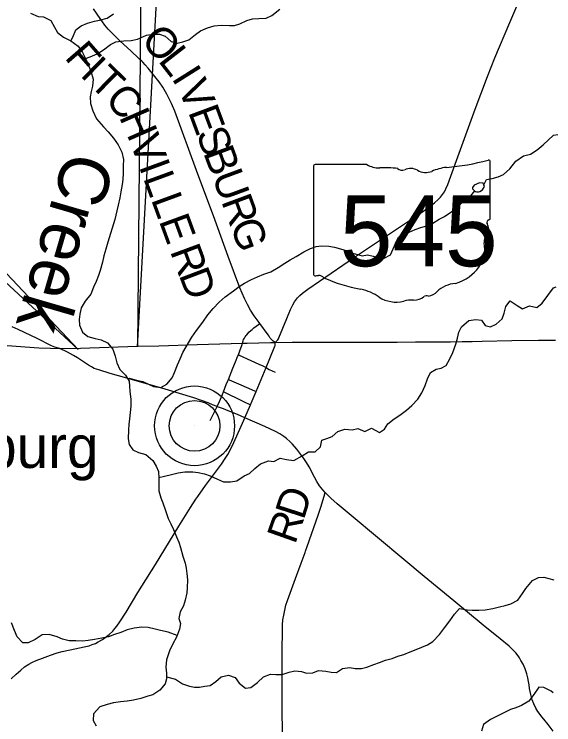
# Model space of a CAD drawing. Extents: x 0 to 34, y 0 to 22.
# Drawn here: x 6.497 to 7.503, y 16.591 to 17.915 of the extents above; entities that cross this region are included whole.
import ezdxf

# ---------------------------------------------------------------- set-up
doc = ezdxf.new("R2010")
doc.units = 0
for name, color, linetype in [('Default', 7, 'Continuous'), ('GM_X_County_Road', 7, 'Continuous'), ('GM_X_County_Road_Text', 7, 'Continuous'), ('GM_X_Minor_Lake', 7, 'Continuous'), ('GM_X_Minor_River', 7, 'Continuous'), ('GM_X_Minor_River_Text', 7, 'Continuous'), ('GM_X_State_Location', 7, 'Continuous'), ('GM_X_State_Route', 7, 'Continuous'), ('GM_X_State_Shield', 7, 'Continuous'), ('GM_X_Township_Road', 7, 'Continuous'), ('GM_X_Township_Road_Text', 7, 'Continuous'), ('GM_X_Unincorporated', 7, 'Continuous'), ('GM_X_Unincorporated_Location', 7, 'Continuous'), ('GM_X_Unincorporated_Text', 7, 'Continuous')]:
    doc.layers.add(name, color=color, linetype=linetype)

msp = doc.modelspace()

# ---------------------------------------------------------------- linework, layer by layer
at = {"layer": 'Default'}
for points in [[(6.7366, 18.3097), (6.7269, 17.2952), (6.7828, 18.3097)], [(6.2148, 17.662), (6.6166, 17.2903), (6.2148, 17.7158)]]:
    msp.add_lwpolyline(points, close=True, dxfattribs=at)
at = {"layer": 'GM_X_County_Road'}
for points in [[(6.9547, 17.3388), (6.9536, 17.3403), (6.9446, 17.3529), (6.9379, 17.3633), (6.9319, 17.3741), (6.9264, 17.3852), (6.9176, 17.4052), (6.8962, 17.4634), (6.8686, 17.5393), (6.8545, 17.5772), (6.8372, 17.6238), (6.7964, 17.7345), (6.7904, 17.7488), (6.7864, 17.7573), (6.782, 17.7656), (6.774, 17.7788), (6.7672, 17.7888), (6.7597, 17.7987), (6.752, 17.8082), (6.7496, 17.8109), (6.7471, 17.8143), (6.7415, 17.8206), (6.7371, 17.8253), (6.7352, 17.8273), (6.7311, 17.8312), (6.7297, 17.8326), (6.7147, 17.8463), (6.6947, 17.8646), (6.6822, 17.8767), (6.6722, 17.8872), (6.6664, 17.8944), (6.6573, 17.9069), (6.6453, 17.9247)], [(6.9838, 17.3036), (6.9801, 17.3059), (6.9779, 17.3076), (6.9745, 17.3117), (6.9721, 17.3153), (6.9703, 17.3178), (6.9547, 17.3388)]]:
    msp.add_lwpolyline(points, dxfattribs=at)
at = {"layer": 'GM_X_Minor_Lake'}
for points in [[(7.3649, 17.5845), (7.3695, 17.5875), (7.3733, 17.594), (7.3707, 17.6004), (7.3639, 17.6009), (7.354, 17.5964), (7.3513, 17.5918)], [(7.3513, 17.5918), (7.3514, 17.5898), (7.3526, 17.5882), (7.3549, 17.5859), (7.357, 17.5843), (7.3595, 17.5837), (7.3624, 17.5837), (7.3649, 17.5845)], [(7.5016, 16.6509), (7.4975, 16.6538), (7.4842, 16.6607), (7.4747, 16.6612), (7.4655, 16.6475), (7.456, 16.6351), (7.4423, 16.6272), (7.432, 16.623), (7.4218, 16.6197), (7.4092, 16.6137), (7.3971, 16.6073), (7.3849, 16.6013), (7.3716, 16.5918), (7.3677, 16.5793)]]:
    msp.add_lwpolyline(points, dxfattribs=at)
at = {"layer": 'GM_X_Minor_River'}
for points in [[(6.6301, 17.8324), (6.6387, 17.8356), (6.652, 17.8408), (6.6638, 17.8487), (6.6768, 17.8582), (6.6867, 17.8631), (6.7019, 17.8653), (6.7155, 17.8659), (6.7273, 17.8682), (6.744, 17.8757), (6.7554, 17.8775), (6.7683, 17.8778), (6.7785, 17.8736), (6.7899, 17.8637), (6.8013, 17.8606), (6.8115, 17.8632), (6.8225, 17.8669), (6.8351, 17.8771), (6.8446, 17.8839), (6.8572, 17.8892), (6.8697, 17.8929), (6.883, 17.8944), (6.8985, 17.8935), (6.908, 17.8935), (6.9179, 17.8968), (6.9308, 17.9032), (6.9411, 17.9062), (6.9533, 17.9069), (6.9669, 17.9076), (6.9772, 17.9125), (6.992, 17.9242)], [(6.5276, 17.917), (6.5423, 17.9108), (6.5518, 17.91), (6.5654, 17.9031), (6.5726, 17.8909), (6.5782, 17.881), (6.5892, 17.8719), (6.6032, 17.865), (6.6164, 17.8554), (6.6247, 17.8436), (6.6307, 17.8311), (6.6364, 17.8181), (6.6401, 17.8086), (6.6446, 17.7938), (6.6434, 17.7805), (6.6411, 17.771), (6.6391, 17.7608), (6.6398, 17.7483), (6.6436, 17.7346), (6.6507, 17.7201), (6.6635, 17.7053), (6.6726, 17.6957), (6.6824, 17.6839), (6.6914, 17.6713), (6.6978, 17.6576), (6.7008, 17.6443), (6.7007, 17.6333), (6.7003, 17.6185), (6.6995, 17.6071), (6.6983, 17.5977), (6.6963, 17.584), (6.6944, 17.573), (6.6913, 17.5594), (6.6886, 17.5484), (6.6847, 17.5324), (6.672, 17.4904), (6.6681, 17.4771), (6.6646, 17.465), (6.6619, 17.4532), (6.6573, 17.4377), (6.6542, 17.4282), (6.65, 17.4172), (6.645, 17.4062), (6.64, 17.3933), (6.6297, 17.3805), (6.6221, 17.3676), (6.6197, 17.3559), (6.6185, 17.346), (6.6193, 17.3357), (6.6249, 17.3228), (6.6347, 17.3148), (6.648, 17.3106), (6.6593, 17.3086), (6.6711, 17.3025), (6.6809, 17.2907), (6.6858, 17.2781), (6.6887, 17.2656), (6.6944, 17.253), (6.7049, 17.2427), (6.7113, 17.2313), (6.7124, 17.2218), (6.7131, 17.2119), (6.7146, 17.1975), (6.7149, 17.185), (6.7137, 17.1728), (6.7125, 17.1614), (6.711, 17.1508), (6.7101, 17.1406), (6.7097, 17.1239)], [(6.6032, 17.865), (6.6066, 17.8722), (6.612, 17.8854), (6.6223, 17.8934), (6.6341, 17.8979), (6.647, 17.902), (6.6565, 17.9038), (6.6706, 17.9075), (6.6824, 17.9158)], [(7.372, 17.5973), (7.3775, 17.6069), (7.3878, 17.6087), (7.3988, 17.6121), (7.4091, 17.6162), (7.4209, 17.6268), (7.432, 17.6411), (7.4461, 17.6513), (7.4594, 17.6543), (7.4719, 17.6622), (7.4826, 17.6713), (7.5023, 17.6895)], [(7.5023, 17.6895), (7.5102, 17.6906)], [(6.7094, 17.2347), (6.7125, 17.2366), (6.7254, 17.2331), (6.7368, 17.2304), (6.7474, 17.2258), (6.7572, 17.2216), (6.7705, 17.2196), (6.7819, 17.226), (6.7914, 17.2373), (6.796, 17.2476), (6.8014, 17.262), (6.8064, 17.2726), (6.8118, 17.2847), (6.8175, 17.2953), (6.8282, 17.3131), (6.837, 17.3256), (6.8489, 17.3415), (6.858, 17.3547), (6.8683, 17.3664), (6.879, 17.3785), (6.8904, 17.3883), (6.9057, 17.3996), (6.9167, 17.4076), (6.9262, 17.4136), (6.9395, 17.4207), (6.9506, 17.4256), (6.9627, 17.4305), (6.9757, 17.435), (6.9894, 17.4433), (7.0015, 17.4508), (7.0114, 17.4572), (7.0228, 17.4636), (7.0369, 17.4723), (7.0495, 17.4786), (7.0601, 17.482), (7.0696, 17.4835), (7.0833, 17.4827), (7.0939, 17.4811), (7.1053, 17.478), (7.1178, 17.4741), (7.1284, 17.4699), (7.1454, 17.4649), (7.1557, 17.4664), (7.1659, 17.4644), (7.1765, 17.4609), (7.1864, 17.4601), (7.1982, 17.4669), (7.2035, 17.4775), (7.2074, 17.4877), (7.2135, 17.4995), (7.2234, 17.5059), (7.2329, 17.5089), (7.2443, 17.5138), (7.2546, 17.5175), (7.2663, 17.5209), (7.2774, 17.5257), (7.2888, 17.5333), (7.2987, 17.5382), (7.3128, 17.5476), (7.323, 17.5555), (7.3364, 17.5687), (7.3482, 17.5763), (7.3553, 17.5856)], [(6.767, 17.0519), (6.7777, 17.0541), (6.7906, 17.0574), (6.8031, 17.0608), (6.8153, 17.0622), (6.8304, 17.0625), (6.8403, 17.0614), (6.8517, 17.059), (6.8623, 17.0548), (6.8763, 17.049), (6.8873, 17.044), (6.9002, 17.0436), (6.9119, 17.0454), (6.9256, 17.0549), (6.9355, 17.0594), (6.9458, 17.0688), (6.9561, 17.0775), (6.9709, 17.0831), (6.9808, 17.0819), (6.9926, 17.0876), (7.0047, 17.0856), (7.0184, 17.0836), (7.034, 17.0923), (7.0454, 17.0998), (7.0579, 17.0994), (7.0682, 17.1088), (7.0702, 17.1217), (7.0797, 17.1243), (7.0895, 17.1281), (7.1002, 17.1375), (7.1135, 17.1416), (7.1272, 17.1408), (7.1374, 17.143), (7.1507, 17.1377), (7.1632, 17.1437), (7.1776, 17.1356), (7.1875, 17.142), (7.1932, 17.1519), (7.205, 17.1613), (7.2157, 17.1681), (7.2283, 17.1771), (7.2382, 17.1858), (7.2496, 17.1979), (7.2569, 17.2096), (7.263, 17.2233), (7.2676, 17.2354), (7.2726, 17.2475), (7.2833, 17.2539), (7.2928, 17.2554), (7.3023, 17.2603), (7.3092, 17.2728), (7.3145, 17.2845), (7.3199, 17.3001), (7.323, 17.3114), (7.3257, 17.3224), (7.3307, 17.3323), (7.344, 17.3444), (7.3573, 17.3462), (7.3679, 17.345), (7.3747, 17.3351), (7.3846, 17.3324), (7.3952, 17.3373), (7.4067, 17.3475), (7.4101, 17.3581), (7.4132, 17.3702), (7.4212, 17.3808), (7.4345, 17.372), (7.4443, 17.3663), (7.4572, 17.3719), (7.4709, 17.3688), (7.4812, 17.3767), (7.5023, 17.4052)], [(7.5023, 17.4052), (7.5071, 17.4069)], [(6.7097, 17.1239), (6.7115, 17.1132), (6.7187, 17.1037), (6.7289, 17.0983), (6.7429, 17.0949), (6.7554, 17.0834), (6.7618, 17.0731), (6.7663, 17.0632), (6.767, 17.0507), (6.7666, 17.037), (6.7669, 17.0268), (6.7703, 17.0142), (6.774, 17.0044), (6.7792, 16.9903), (6.7845, 16.9755), (6.789, 16.9656), (6.7939, 16.9549), (6.7999, 16.9416), (6.804, 16.9317), (6.8074, 16.9218), (6.8115, 16.9055), (6.8156, 16.8926), (6.8178, 16.8827), (6.8193, 16.8728), (6.82, 16.8614), (6.8199, 16.8466), (6.8191, 16.8371), (6.816, 16.8235), (6.8129, 16.8129), (6.8068, 16.8019), (6.8041, 16.7894), (6.8071, 16.7799), (6.8055, 16.7692), (6.7997, 16.7545), (6.7932, 16.7423), (6.7867, 16.7291), (6.781, 16.7124), (6.7801, 16.6984), (6.7812, 16.6874), (6.7812, 16.6771), (6.7788, 16.6676), (6.7685, 16.6559), (6.7556, 16.6473), (6.7461, 16.6443), (6.7332, 16.6405), (6.7195, 16.6372), (6.7081, 16.6353), (6.6952, 16.6339), (6.6827, 16.6324), (6.6709, 16.6291), (6.6568, 16.625), (6.645, 16.6117), (6.6446, 16.5992), (6.6502, 16.5893)], [(6.7812, 16.6809), (6.7979, 16.6763), (6.8107, 16.6675), (6.824, 16.6632), (6.8335, 16.6613), (6.8429, 16.6612), (6.8528, 16.6631), (6.8627, 16.6642), (6.873, 16.6721), (6.8829, 16.6804), (6.8965, 16.6838), (6.909, 16.6791), (6.9166, 16.6685), (6.9283, 16.6597), (6.9382, 16.6608), (6.9507, 16.6702), (6.9618, 16.6808), (6.9747, 16.6857), (6.985, 16.6852), (6.9963, 16.6848), (7.0096, 16.6893), (7.0203, 16.6915), (7.0324, 16.6903), (7.0419, 16.6876), (7.0537, 16.6879), (7.0643, 16.6921), (7.078, 16.6912), (7.0878, 16.6893), (7.0977, 16.6885), (7.1091, 16.6964), (7.1228, 16.6978), (7.1326, 16.6959), (7.1444, 16.6962), (7.1546, 16.6988), (7.1676, 16.7037), (7.1778, 16.7074), (7.1892, 16.7116), (7.2014, 16.7149), (7.212, 16.719), (7.2234, 16.7224), (7.2348, 16.7273), (7.2462, 16.7318), (7.2569, 16.7359), (7.2675, 16.7404), (7.2774, 16.7464), (7.2896, 16.7593), (7.2992, 16.7718), (7.3091, 16.785), (7.3175, 16.7975), (7.327, 16.8077), (7.3411, 16.8053), (7.3506, 16.8045), (7.3627, 16.8045), (7.3748, 16.8056), (7.3889, 16.8078), (7.4014, 16.8107), (7.4117, 16.8137), (7.4223, 16.8167), (7.4356, 16.8235), (7.4444, 16.8356), (7.4505, 16.8454), (7.4631, 16.8598), (7.4742, 16.8654), (7.484, 16.8665), (7.5025, 16.861)], [(6.8009, 16.7574), (6.7842, 16.7636), (6.7698, 16.7671), (6.76, 16.7695), (6.7467, 16.7722), (6.7353, 16.7734), (6.7209, 16.7712), (6.708, 16.7682), (6.6958, 16.7633), (6.684, 16.7592), (6.6734, 16.7551), (6.6605, 16.7525), (6.6472, 16.7499), (6.635, 16.7484), (6.6244, 16.7473), (6.6123, 16.7474), (6.5997, 16.7478), (6.5876, 16.7509), (6.5774, 16.7548), (6.5626, 16.7594), (6.5497, 16.7587), (6.5364, 16.7501), (6.5235, 16.744), (6.5136, 16.7437), (6.503, 16.7548), (6.4978, 16.7666), (6.4925, 16.781)]]:
    msp.add_lwpolyline(points, dxfattribs=at)
at = {"layer": 'GM_X_State_Route'}
for points in [[(6.9838, 17.3036), (6.9869, 17.3066), (6.9887, 17.3086), (6.9896, 17.3101), (6.9905, 17.3119), (7.005, 17.3479), (7.0124, 17.3651), (7.0164, 17.3735), (7.0195, 17.379), (7.0213, 17.3816), (7.0252, 17.3865), (7.0296, 17.391), (7.0344, 17.3951), (7.0444, 17.4025), (7.1316, 17.4623), (7.2039, 17.5107), (7.258, 17.547), (7.2707, 17.5559), (7.2804, 17.5635), (7.2873, 17.5697), (7.2916, 17.5741), (7.2955, 17.5788), (7.2988, 17.5839), (7.3017, 17.5893), (7.3052, 17.5979), (7.3191, 17.6357), (7.356, 17.7379), (7.3789, 17.799), (7.3928, 17.8336), (7.4205, 17.8995), (7.4448, 17.9567)], [(6.9272, 17.1631), (6.9133, 17.1691), (6.896, 17.176), (6.8874, 17.1795), (6.878, 17.1831), (6.8757, 17.184), (6.8671, 17.1873), (6.8585, 17.1908), (6.8322, 17.2), (6.8056, 17.2086), (6.7788, 17.2164), (6.707, 17.2366), (6.676, 17.2456), (6.6549, 17.2522), (6.6466, 17.2552), (6.6416, 17.2577), (6.6357, 17.2611), (6.6282, 17.2663), (6.6153, 17.2746), (6.6076, 17.2793), (6.5965, 17.2854), (6.5822, 17.2923), (6.5734, 17.2945), (6.5667, 17.2969), (6.5405, 17.3107), (6.5049, 17.3275), (6.4937, 17.3328)], [(6.4845, 17.2979), (6.5433, 17.2935), (6.565, 17.2925), (6.5822, 17.2923), (6.5866, 17.2922), (6.6207, 17.2929), (6.7263, 17.2962), (6.7667, 17.2971), (6.8382, 17.2995), (6.9225, 17.302), (6.9259, 17.3022), (6.9313, 17.3024), (6.9748, 17.3034), (6.9808, 17.3035)], [(6.836, 17.0114), (6.8395, 17.0166), (6.8538, 17.037), (6.8834, 17.0769), (6.8905, 17.0871), (6.8954, 17.0949), (6.8998, 17.103), (6.9064, 17.1171), (6.92, 17.1477), (6.9252, 17.1585), (6.9272, 17.1631), (6.9377, 17.1874), (6.9409, 17.1949), (6.9479, 17.2118), (6.9665, 17.2567), (6.9819, 17.2937), (6.983, 17.2964), (6.9835, 17.298), (6.9837, 17.2999), (6.9838, 17.3036)], [(6.9808, 17.3035), (6.9838, 17.3036), (7.0155, 17.304), (7.0899, 17.3042), (7.1396, 17.3038), (7.1706, 17.3039), (7.2109, 17.3042), (7.245, 17.3044), (7.2666, 17.3044), (7.2853, 17.3044), (7.3101, 17.3047), (7.3318, 17.3051), (7.3504, 17.3054), (7.369, 17.3057), (7.4247, 17.3071), (7.4743, 17.3076), (7.4973, 17.3078), (7.5055, 17.3078)], [(7.5017, 16.5795), (7.4918, 16.5919), (7.4842, 16.6016), (7.4805, 16.6063), (7.4771, 16.6106), (7.4729, 16.6163), (7.4691, 16.6225), (7.4651, 16.6304), (7.4625, 16.6375), (7.4612, 16.6428), (7.46, 16.6475), (7.4575, 16.6591), (7.4567, 16.6656), (7.4553, 16.6718), (7.454, 16.679), (7.4521, 16.6864), (7.449, 16.6953), (7.4456, 16.7039), (7.4414, 16.7111), (7.4385, 16.7158), (7.436, 16.7197), (7.4316, 16.7254), (7.4256, 16.7318), (7.4192, 16.7376), (7.4026, 16.7512), (7.3711, 16.7766), (7.3162, 16.8221), (7.261, 16.8673), (7.223, 16.8994), (7.1254, 16.9813), (7.099, 17.0031), (7.0874, 17.0134), (7.0785, 17.0221), (7.0767, 17.0241), (7.0722, 17.0291), (7.0664, 17.0365), (7.0613, 17.0443), (7.0567, 17.0524), (7.0466, 17.0717), (7.042, 17.0797), (7.037, 17.0875), (7.0316, 17.095), (7.0239, 17.1047), (7.0157, 17.114), (7.0115, 17.1184), (7.0047, 17.1247), (6.9999, 17.1285), (6.9922, 17.1333), (6.9841, 17.1376), (6.9646, 17.147), (6.9272, 17.1631)], [(6.7351, 16.8494), (6.7604, 16.8901), (6.8044, 16.9615), (6.8257, 16.9959), (6.836, 17.0114)], [(6.492, 16.6769), (6.5008, 16.6856), (6.5095, 16.6933), (6.5168, 16.699), (6.5247, 16.7041), (6.5301, 16.7071), (6.5386, 16.7111), (6.5499, 16.7155), (6.5652, 16.7212), (6.5775, 16.725), (6.5865, 16.7275), (6.6017, 16.7308), (6.628, 16.7363), (6.637, 16.7386), (6.6429, 16.7406), (6.6486, 16.7429), (6.6541, 16.7456), (6.6621, 16.7502), (6.6671, 16.7537), (6.6743, 16.7594), (6.681, 16.7658), (6.6851, 16.7704), (6.6889, 16.7752), (6.6942, 16.7829), (6.7058, 16.8013), (6.7278, 16.8376), (6.7351, 16.8494)]]:
    msp.add_lwpolyline(points, dxfattribs=at)
at = {"layer": 'GM_X_State_Shield'}
for p, q in [((7.0547, 17.6313), (7.0547, 17.4312)), ((7.1545, 17.6348), (7.058, 17.6348)), ((7.3843, 17.5351), (7.3843, 17.6398)), ((7.3843, 17.5351), (7.3843, 17.5351))]:
    msp.add_line(p, q, dxfattribs=at)
for centre, major_axis, start_param, end_param in [((7.2669, 17.9076), (0.3495, 0), 4.814394, 5.042369), ((7.3807, 17.6402), (0.00367, 0), 6.141152, 7.989035), ((7.0585, 17.6318), (0.00382, 0), 1.712693, 3.28349), ((7.1775, 17.658), (0.037, 0), 4.042523, 4.731795), ((7.3115, 17.5737), (0.0703, 0), 1.699011, 2.107814), ((7.1898, 17.5224), (0.133, 0), 1.404758, 1.657858), ((7.2199, 17.6328), (0.0107, 0), 3.836095, 5.185415), ((7.2356, 17.6097), (0.0222, 0), 0.950623, 2.079405), ((7.2643, 17.6414), (0.0267, 0), 4.081561, 5.145723), ((7.3835, 17.5274), (0.00568, 0), 1.883978, 3.671073), ((7.3473, 17.5141), (0.0341, 0), 5.934695, 6.695948), ((7.3804, 17.5347), (0.00393, 0), 5.05454, 6.418171), ((7.3975, 17.4913), (0.0248, 0), 2.387724, 3.262537), ((7.2865, 17.4779), (0.0874, 0), 5.101752, 6.440018), ((7.0585, 17.4308), (0.00385, 0), 3.00124, 4.508301), ((7.0591, 17.4513), (0.0294, 0), 4.665946, 4.897461), ((7.0651, 17.4197), (0.0106, 0), 0.519207, 1.627899), ((7.199, 17.5995), (0.2524, 0), 4.195997, 4.488961), ((7.3234, 17.375), (0.0479, 0), 1.647645, 2.488434), ((7.1237, 17.3413), (0.079, 0), 0.823519, 1.323587), ((7.2627, 17.4118), (0.0282, 0), 4.937069, 5.64225), ((7.2091, 17.4187), (0.0501, 0), 4.026481, 4.996735), ((7.2381, 17.3495), (0.0412, 0), 1.495662, 1.94098), ((7.2417, 17.4037), (0.0267, 0), 4.691044, 5.507374), ((7.2659, 17.3843), (0.00752, 0), 1.147584, 2.315152)]:
    msp.add_ellipse(centre, major_axis=major_axis, ratio=0.8, start_param=start_param, end_param=end_param, dxfattribs=at)
at = {"layer": 'GM_X_Township_Road'}
msp.add_line((6.8622, 17.1583), (6.8757, 17.184), dxfattribs=at)
for points in [[(6.9225, 17.302), (6.9231, 17.3048), (6.9238, 17.3067), (6.9248, 17.3088), (6.9264, 17.3116), (6.9278, 17.3137), (6.9296, 17.3164), (6.9307, 17.3177), (6.933, 17.3205), (6.9346, 17.3223), (6.938, 17.3254), (6.9404, 17.3275), (6.944, 17.3305), (6.9525, 17.3371), (6.9547, 17.3388)], [(6.915, 17.2804), (6.9186, 17.2894), (6.9214, 17.2977), (6.9225, 17.302)], [(6.8964, 17.2343), (6.9048, 17.2557), (6.9097, 17.2671), (6.9143, 17.2786), (6.915, 17.2804)], [(6.915, 17.2804), (6.9162, 17.2799), (6.9382, 17.2696), (6.9529, 17.2632), (6.9608, 17.2597), (6.9665, 17.2567)], [(6.9665, 17.2567), (6.9692, 17.2551), (6.9726, 17.2533), (6.9833, 17.2481)], [(6.8871, 17.2115), (6.8924, 17.2249), (6.8954, 17.2319), (6.8964, 17.2343)], [(6.8964, 17.2343), (6.8976, 17.2338), (6.9107, 17.2284), (6.9194, 17.2246), (6.9297, 17.2199), (6.9449, 17.2132), (6.9479, 17.2118)], [(6.8757, 17.184), (6.8797, 17.1933), (6.8852, 17.2067), (6.8871, 17.2115)], [(6.8871, 17.2115), (6.8889, 17.2107), (6.921, 17.1955), (6.9269, 17.1925), (6.9351, 17.1887), (6.9377, 17.1874)], [(6.9976, 16.5072), (6.9968, 16.6284), (6.9964, 16.6753), (6.9969, 16.7339), (6.997, 16.7618), (6.9975, 16.7773), (6.9981, 16.7866), (6.9995, 16.7956), (7.0014, 16.8047), (7.0037, 16.8138), (7.0066, 16.8227), (7.0214, 16.8636), (7.0319, 16.8926), (7.0392, 16.9119), (7.0401, 16.9147), (7.0431, 16.9231), (7.0636, 16.9816), (7.0686, 16.9965), (7.0748, 17.0173), (7.0767, 17.0241)]]:
    msp.add_lwpolyline(points, dxfattribs=at)
at = {"layer": 'GM_X_Unincorporated'}
for radius in [0.0744, 0.0472]:
    msp.add_circle((6.8334, 17.1481), radius, dxfattribs=at)
at = {"layer": 'GM_X_Unincorporated_Location'}
msp.add_line((6.8334, 17.1481), (6.8334, 17.1481), dxfattribs=at)

# ---------------------------------------------------------------- texts
at = {"layer": 'GM_X_County_Road_Text'}
for s, rotation, p in [('O', 312.4776, (6.7313, 17.8641)), ('F', 311.0357, (6.5897, 17.8335)), ('L', 307.8359, (6.7642, 17.8281)), ('I', 315.8009, (6.6184, 17.8008)), ('T', 315.6819, (6.6351, 17.7846)), ('I', 302.1874, (6.7895, 17.7958)), ('V', 294.0098, (6.8009, 17.7779)), ('C', 309.8321, (6.6644, 17.756)), ('H', 293.6248, (6.6921, 17.7238)), ('E', 290.376, (6.8209, 17.7331)), ('V', 290.1919, (6.7118, 17.6788)), ('S', 290.3014, (6.8357, 17.6933)), ('B', 290.3002, (6.849, 17.6573)), ('I', 290.1705, (6.7291, 17.6319)), ('L', 290.1578, (6.7371, 17.61)), ('U', 290.3027, (6.8652, 17.6136)), ('L', 290.1578, (6.7518, 17.5701)), ('R', 290.3053, (6.8825, 17.5667)), ('E', 290.1613, (6.7664, 17.5302)), ('G', 290.3002, (6.8987, 17.5229)), ('R', 290.2659, (6.7871, 17.4737)), ('D', 290.7654, (6.8035, 17.4295))]:
    msp.add_text(s, height=0.0568, rotation=rotation, dxfattribs=at).set_placement(p)
at = {"layer": 'GM_X_Minor_River_Text'}
msp.add_text('Creek', height=0.09473, rotation=253.7653, dxfattribs=at).set_placement((6.5949, 17.6633))
at = {"layer": 'GM_X_State_Location'}
for s in ['s', 'r']:
    msp.add_text(s, height=0.000189, dxfattribs=at).set_placement((7.2158, 17.518))
msp.add_text('545', height=0.000189, rotation=0, dxfattribs=at).set_placement((7.149, 17.5042))
at = {"layer": 'GM_X_State_Shield'}
msp.add_text('545', height=0.13184, dxfattribs=at).set_placement((7.1039, 17.4453))
at = {"layer": 'GM_X_Township_Road_Text'}
for s, rotation, p in [('D', 72.1321, (7.0365, 16.9712)), ('R', 70.5047, (7.0204, 16.9256))]:
    msp.add_text(s, height=0.0568, rotation=rotation, dxfattribs=at).set_placement(p)
at = {"layer": 'GM_X_Unincorporated_Text'}
msp.add_text('Olivesburg', height=0.07898, rotation=0, dxfattribs=at).set_placement((6.1498, 17.0697))

doc.saveas('drawing.dxf')
